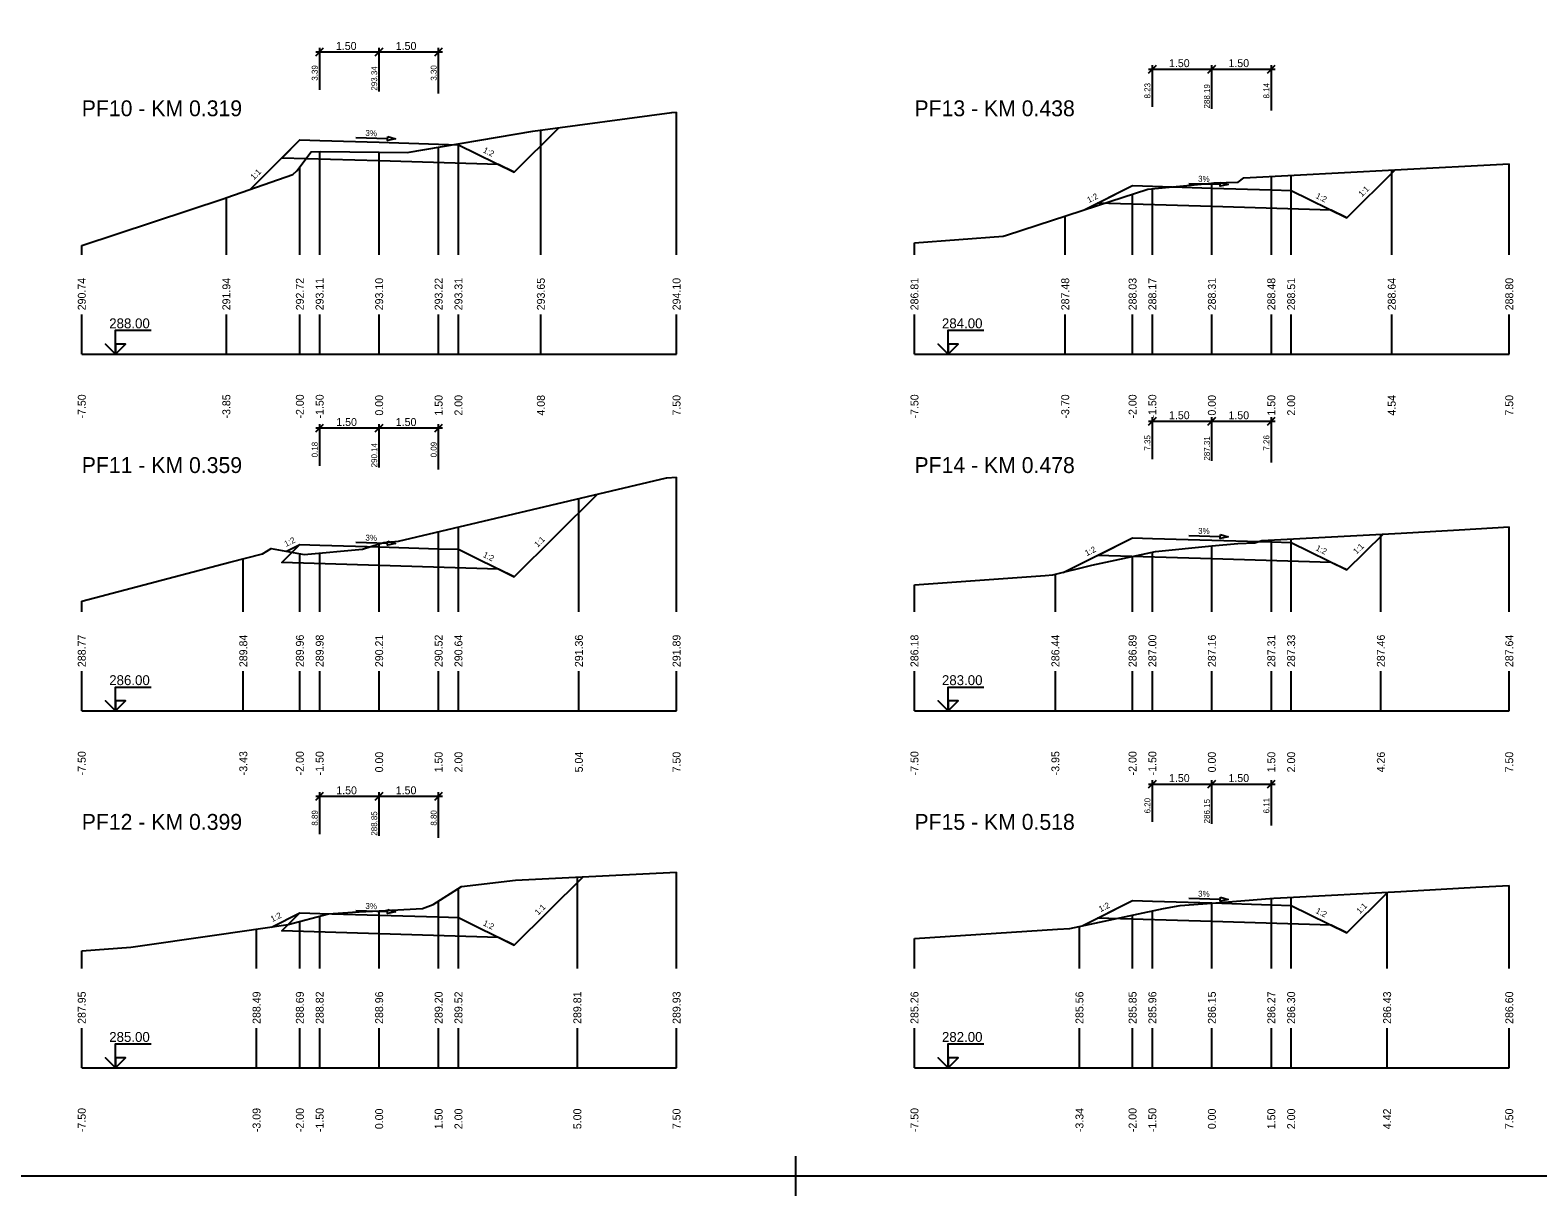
# Model space of a CAD drawing. Extents: x -5 to 1265, y -2 to 602.
# Drawn here: x 647 to 1027.2, y -2.3 to 291.7 of the extents above; entities that cross this region are included whole.
import ezdxf

# ---------------------------------------------------------------- set-up
doc = ezdxf.new("R2010")
doc.units = 0
for name, color, linetype in [('KOTA', 7, 'Continuous'), ('KOTA_DELKY', 7, 'Continuous'), ('KOTA_DELKY_CONT', 7, 'Continuous'), ('NS_TELESO_VOZOVKY', 7, 'Continuous'), ('NS_V_PF', 7, 'Continuous'), ('REZY_PF_PUVODNI', 7, 'Continuous'), ('SESTAVY_REZU_PF', 7, 'Continuous'), ('SKLON', 7, 'Continuous'), ('SVK', 7, 'Continuous')]:
    doc.layers.add(name, color=color, linetype=linetype)

msp = doc.modelspace()

# ---------------------------------------------------------------- linework, layer by layer
for p, q in [((840, 7.67), (840, -2.33)), ((840, 7.67), (840, -2.33)), ((840, 7.67), (840, -2.33)), ((840, 7.67), (840, -2.33)), ((840, 7.67), (840, -2.33)), ((840, 7.67), (840, -2.33)), ((840, 7.67), (840, -2.33)), ((840, 7.67), (840, -2.33)), ((840, 7.67), (840, -2.33)), ((840, 7.67), (840, -2.33)), ((840, 7.67), (840, -2.33)), ((840, 7.67), (840, -2.33)), ((845, 2.67), (835, 2.67)), ((845, 2.67), (835, 2.67)), ((845, 2.67), (835, 2.67)), ((845, 2.67), (835, 2.67)), ((845, 2.67), (835, 2.67)), ((845, 2.67), (835, 2.67)), ((845, 2.67), (835, 2.67)), ((845, 2.67), (835, 2.67)), ((845, 2.67), (835, 2.67)), ((845, 2.67), (835, 2.67)), ((845, 2.67), (835, 2.67)), ((845, 2.67), (835, 2.67))]:
    msp.add_line(p, q)
msp.add_lwpolyline([(0, 596.67), (1260, 596.67), (1260, 2.67), (0, 2.67)], close=True)
at = {"layer": 'KOTA'}
for points in [[(668.51, 210), (666.01, 212.5), (668.51, 210), (668.51, 216), (677.51, 216)], [(878.51, 210), (876.01, 212.5), (878.51, 210), (878.51, 216), (887.51, 216)], [(668.51, 210), (671.01, 212.5), (668.51, 212.5), (668.51, 210)], [(668.51, 210), (671.01, 212.5), (668.51, 212.5)], [(878.51, 210), (881.01, 212.5), (878.51, 212.5), (878.51, 210)], [(878.51, 210), (881.01, 212.5), (878.51, 212.5)], [(668.51, 120), (666.01, 122.5), (668.51, 120), (668.51, 126), (677.51, 126)], [(878.51, 120), (876.01, 122.5), (878.51, 120), (878.51, 126), (887.51, 126)], [(668.51, 120), (671.01, 122.5), (668.51, 122.5), (668.51, 120)], [(668.51, 120), (671.01, 122.5), (668.51, 122.5)], [(878.51, 120), (881.01, 122.5), (878.51, 122.5), (878.51, 120)], [(878.51, 120), (881.01, 122.5), (878.51, 122.5)], [(668.51, 30), (666.01, 32.5), (668.51, 30), (668.51, 36), (677.51, 36)], [(878.51, 30), (876.01, 32.5), (878.51, 30), (878.51, 36), (887.51, 36)], [(668.51, 30), (671.01, 32.5), (668.51, 32.5), (668.51, 30)], [(668.51, 30), (671.01, 32.5), (668.51, 32.5)], [(878.51, 30), (881.01, 32.5), (878.51, 32.5), (878.51, 30)], [(878.51, 30), (881.01, 32.5), (878.51, 32.5)]]:
    msp.add_lwpolyline(points, dxfattribs=at)
at = {"layer": 'KOTA_DELKY'}
for points in [[(719, 285.22), (721, 287.22)], [(719, 286.22), (736, 286.22)], [(720, 276.67), (720, 287.22)], [(734, 285.22), (736, 287.22)], [(734, 285.22), (736, 287.22)], [(734, 286.22), (751, 286.22)], [(735, 276.22), (735, 287.22)], [(735, 276.22), (735, 287.22)], [(749, 285.22), (751, 287.22)], [(750, 275.77), (750, 287.22)], [(929, 280.89), (931, 282.89)], [(929, 281.89), (946, 281.89)], [(930, 272.34), (930, 282.89)], [(944, 280.89), (946, 282.89)], [(944, 280.89), (946, 282.89)], [(944, 281.89), (961, 281.89)], [(945, 271.89), (945, 282.89)], [(945, 271.89), (945, 282.89)], [(959, 280.89), (961, 282.89)], [(960, 271.44), (960, 282.89)], [(929, 192.07), (931, 194.07)], [(930, 183.52), (930, 194.07)], [(944, 192.07), (946, 194.07)], [(944, 192.07), (946, 194.07)], [(945, 183.07), (945, 194.07)], [(945, 183.07), (945, 194.07)], [(959, 192.07), (961, 194.07)], [(960, 182.62), (960, 194.07)], [(719, 190.36), (721, 192.36)], [(719, 191.36), (736, 191.36)], [(720, 181.81), (720, 192.36)], [(734, 190.36), (736, 192.36)], [(734, 190.36), (736, 192.36)], [(734, 191.36), (751, 191.36)], [(735, 181.36), (735, 192.36)], [(735, 181.36), (735, 192.36)], [(749, 190.36), (751, 192.36)], [(750, 180.91), (750, 192.36)], [(929, 193.07), (946, 193.07)], [(944, 193.07), (961, 193.07)], [(719, 97.46), (721, 99.46)], [(720, 88.91), (720, 99.46)], [(734, 97.46), (736, 99.46)], [(734, 97.46), (736, 99.46)], [(735, 88.46), (735, 99.46)], [(735, 88.46), (735, 99.46)], [(749, 97.46), (751, 99.46)], [(750, 88.01), (750, 99.46)], [(929, 100.55), (931, 102.55)], [(929, 101.55), (946, 101.55)], [(930, 92), (930, 102.55)], [(944, 100.55), (946, 102.55)], [(944, 100.55), (946, 102.55)], [(944, 101.55), (961, 101.55)], [(945, 91.55), (945, 102.55)], [(945, 91.55), (945, 102.55)], [(959, 100.55), (961, 102.55)], [(960, 91.1), (960, 102.55)], [(719, 98.46), (736, 98.46)], [(734, 98.46), (751, 98.46)]]:
    msp.add_lwpolyline(points, dxfattribs=at)
at = {"layer": 'NS_TELESO_VOZOVKY'}
for points in [[(735, 263.42), (750, 262.97), (755, 262.82), (769.01, 255.89), (765.11, 257.82), (735, 258.72), (710.44, 259.46), (715, 264.02), (720, 263.87), (735, 263.42)], [(945, 251.89), (960, 251.44), (965, 251.29), (979.01, 244.36), (975.11, 246.28), (945, 247.19), (916.13, 248.05), (925, 252.49), (930, 252.34), (945, 251.89)], [(945, 163.07), (960, 162.62), (965, 162.47), (979.01, 155.54), (975.11, 157.46), (945, 158.37), (916.13, 159.23), (925, 163.67), (930, 163.52), (945, 163.07)], [(735, 161.36), (750, 160.91), (755, 160.76), (769.01, 153.83), (765.11, 155.75), (735, 156.66), (710.44, 157.39), (715, 161.96), (720, 161.81), (735, 161.36)], [(735, 68.46), (750, 68.01), (755, 67.86), (769.01, 60.92), (765.11, 62.85), (735, 63.76), (710.44, 64.49), (715, 69.06), (720, 68.91), (735, 68.46)], [(945, 71.55), (960, 71.1), (965, 70.95), (979.01, 64.02), (975.11, 65.95), (945, 66.85), (916.13, 67.72), (925, 72.15), (930, 72), (945, 71.55)]]:
    msp.add_lwpolyline(points, dxfattribs=at)
at = {"layer": 'NS_V_PF'}
for points in [[(702.5, 251.53), (715, 264.02), (720, 263.87), (735, 263.42), (750, 262.97), (755, 262.82), (769.01, 255.89), (780.35, 267.11)], [(912.82, 246.4), (925, 252.49), (930, 252.34), (945, 251.89), (960, 251.44), (965, 251.29), (979.01, 244.36), (991.25, 256.48)], [(711.6, 160.26), (715, 161.96), (720, 161.81), (735, 161.36), (750, 160.91), (755, 160.76), (769.01, 153.83), (790.07, 174.68)], [(907.54, 154.94), (925, 163.67), (930, 163.52), (945, 163.07), (960, 162.62), (965, 162.47), (979.01, 155.54), (988.16, 164.59)], [(707.85, 65.48), (715, 69.06), (720, 68.91), (735, 68.46), (750, 68.01), (755, 67.86), (769.01, 60.92), (786.41, 78.15)], [(912.29, 65.79), (925, 72.15), (930, 72), (945, 71.55), (960, 71.1), (965, 70.95), (979.01, 64.02), (989.41, 74.31)]]:
    msp.add_lwpolyline(points, dxfattribs=at)
at = {"layer": 'REZY_PF_PUVODNI'}
for points in [[(660, 237.41), (695.94, 249.22), (696.61, 249.46), (713.21, 255.28), (714.28, 256.24), (717.84, 261.04), (720.19, 261.14), (735, 260.97), (742.05, 260.88), (773.75, 266.24), (808.8, 270.91), (810, 271)], [(870, 238.09), (892.4, 239.76), (893.21, 240.02), (916.12, 247.47), (928.82, 251.57), (945, 253.14), (945, 253.14), (945.48, 253.19), (951.62, 253.4), (953.05, 254.48), (991.15, 256.47), (1020, 257.98)], [(660, 147.68), (697.37, 157.48), (705.58, 159.64), (707.74, 160.98), (716.1, 159.41), (730.84, 160.8), (735, 162.11), (736.18, 162.48), (739.91, 162.8), (807.5, 178.8), (807.55, 178.82), (810, 178.93)], [(870, 151.77), (902.92, 154.14), (904.89, 154.28), (914.69, 156.72), (930.75, 160.18), (945, 161.6), (951.52, 162.26), (955.87, 162.42), (957.63, 162.94), (992.77, 164.84), (1007.34, 165.63), (1020, 166.43)], [(660, 59.5), (672.37, 60.43), (694.07, 63.52), (712.04, 66.08), (722.25, 68.81), (728.29, 69.23), (735, 69.56), (745.96, 70.11), (748.61, 71.15), (755.76, 75.74), (769.41, 77.32), (784.52, 78.06), (810, 79.3)], [(870, 62.59), (906.03, 64.92), (909.17, 65.13), (932.77, 70.17), (936.99, 70.9), (945, 71.52), (945, 71.52), (960.63, 72.74), (964.03, 72.94), (992.63, 74.48), (1011.55, 75.51), (1020, 75.98)]]:
    msp.add_lwpolyline(points, dxfattribs=at)
at = {"layer": 'SESTAVY_REZU_PF'}
for points in [[(660, 210), (810, 210)], [(870, 210), (1020, 210)], [(660, 120), (810, 120)], [(870, 120), (1020, 120)], [(660, 30), (810, 30)], [(870, 30), (1020, 30)]]:
    msp.add_lwpolyline(points, dxfattribs=at)
at = {"layer": 'SKLON'}
for points in [[(729.15, 264.6), (737.14, 264.36)], [(737.16, 264.86), (739.14, 264.3), (737.13, 263.86), (737.16, 264.86)], [(939.15, 253.06), (947.14, 252.82)], [(947.16, 253.32), (949.14, 252.76), (947.13, 252.32), (947.16, 253.32)], [(939.15, 164.24), (947.14, 164)], [(947.16, 164.5), (949.14, 163.94), (947.13, 163.5), (947.16, 164.5)], [(729.15, 162.53), (737.14, 162.29)], [(737.16, 162.79), (739.14, 162.23), (737.13, 161.79), (737.16, 162.79)], [(939.15, 72.73), (947.14, 72.49)], [(947.16, 72.98), (949.14, 72.43), (947.13, 71.99), (947.16, 72.98)], [(729.15, 69.63), (737.14, 69.39)], [(737.16, 69.89), (739.14, 69.33), (737.13, 68.89), (737.16, 69.89)]]:
    msp.add_lwpolyline(points, dxfattribs=at)
for points in [[(737.16, 264.86), (739.14, 264.3), (737.13, 263.86)], [(947.16, 253.32), (949.14, 252.76), (947.13, 252.32)], [(947.16, 164.5), (949.14, 163.94), (947.13, 163.5)], [(737.16, 162.79), (739.14, 162.23), (737.13, 161.79)], [(947.16, 72.98), (949.14, 72.43), (947.13, 71.99)], [(737.16, 69.89), (739.14, 69.33), (737.13, 68.89)]]:
    msp.add_lwpolyline(points, close=True, dxfattribs=at)
at = {"layer": 'SVK'}
for points in [[(810, 235), (810, 271)], [(775.78, 235), (775.78, 266.51)], [(755, 235), (755, 263.07)], [(720, 235), (720, 261.13)], [(735, 235), (735, 260.97)], [(750, 235), (750, 262.22)], [(715, 235), (715, 257.21)], [(960, 235), (960, 254.84)], [(965, 235), (965, 255.11)], [(990.36, 235), (990.36, 256.43)], [(1020, 235), (1020, 257.98)], [(930, 235), (930, 251.69)], [(945, 235), (945, 253.14)], [(696.47, 235), (696.47, 249.41)], [(925, 235), (925, 250.34)], [(908.02, 235), (908.02, 244.84)], [(660, 235), (660, 237.41)], [(870, 235), (870, 238.09)], [(660, 210), (660, 220)], [(696.47, 210), (696.47, 220)], [(715, 210), (715, 220)], [(720, 210), (720, 220)], [(735, 210), (735, 220)], [(750, 210), (750, 220)], [(755, 210), (755, 220)], [(775.78, 210), (775.78, 220)], [(810, 210), (810, 220)], [(870, 210), (870, 220)], [(908.02, 210), (908.02, 220)], [(925, 210), (925, 220)], [(930, 210), (930, 220)], [(945, 210), (945, 220)], [(960, 210), (960, 220)], [(965, 210), (965, 220)], [(990.36, 210), (990.36, 220)], [(1020, 210), (1020, 220)], [(810, 145), (810, 178.93)], [(785.37, 145), (785.37, 173.57)], [(750, 145), (750, 165.19)], [(755, 145), (755, 166.38)], [(987.62, 145), (987.62, 164.56)], [(1020, 145), (1020, 166.43)], [(720, 145), (720, 159.78)], [(735, 145), (735, 162.11)], [(930, 145), (930, 160.02)], [(945, 145), (945, 161.6)], [(960, 145), (960, 163.06)], [(965, 145), (965, 163.34)], [(700.74, 145), (700.74, 158.37)], [(715, 145), (715, 159.62)], [(925, 145), (925, 158.94)], [(905.54, 145), (905.54, 154.44)], [(870, 145), (870, 151.77)], [(660, 145), (660, 147.68)], [(660, 120), (660, 130)], [(700.74, 120), (700.74, 130)], [(715, 120), (715, 130)], [(720, 120), (720, 130)], [(735, 120), (735, 130)], [(750, 120), (750, 130)], [(755, 120), (755, 130)], [(785.37, 120), (785.37, 130)], [(810, 120), (810, 130)], [(870, 120), (870, 130)], [(905.54, 120), (905.54, 130)], [(925, 120), (925, 130)], [(930, 120), (930, 130)], [(945, 120), (945, 130)], [(960, 120), (960, 130)], [(965, 120), (965, 130)], [(987.62, 120), (987.62, 130)], [(1020, 120), (1020, 130)], [(784.98, 55), (784.98, 78.08)], [(810, 55), (810, 79.3)], [(755, 55), (755, 75.25)], [(960, 55), (960, 72.69)], [(965, 55), (965, 72.99)], [(989.2, 55), (989.2, 74.3)], [(1020, 55), (1020, 75.98)], [(735, 55), (735, 69.56)], [(750, 55), (750, 72.04)], [(925, 55), (925, 68.51)], [(930, 55), (930, 69.58)], [(945, 55), (945, 71.52)], [(704.08, 55), (704.08, 64.94)], [(715, 55), (715, 66.87)], [(720, 55), (720, 68.21)], [(911.61, 55), (911.61, 65.65)], [(870, 55), (870, 62.59)], [(660, 55), (660, 59.5)], [(660, 30), (660, 40)], [(704.08, 30), (704.08, 40)], [(715, 30), (715, 40)], [(720, 30), (720, 40)], [(735, 30), (735, 40)], [(750, 30), (750, 40)], [(755, 30), (755, 40)], [(784.98, 30), (784.98, 40)], [(810, 30), (810, 40)], [(870, 30), (870, 40)], [(911.61, 30), (911.61, 40)], [(925, 30), (925, 40)], [(930, 30), (930, 40)], [(945, 30), (945, 40)], [(960, 30), (960, 40)], [(965, 30), (965, 40)], [(989.2, 30), (989.2, 40)], [(1020, 30), (1020, 40)]]:
    msp.add_lwpolyline(points, dxfattribs=at)

# ---------------------------------------------------------------- texts
at = {"layer": 'KOTA'}
for s, p in [('288.00', (666.93, 216.5)), ('284.00', (876.93, 216.5)), ('286.00', (666.93, 126.5)), ('283.00', (876.93, 126.5)), ('285.00', (666.93, 36.5)), ('282.00', (876.93, 36.5))]:
    msp.add_text(s, height=2.5, dxfattribs=at).set_placement(p)
at = {"layer": 'KOTA_DELKY'}
for p in [(724.1, 286.72), (739.19, 286.72), (934.19, 282.39), (949.19, 282.39), (934.19, 193.57), (949.19, 193.57), (724.19, 191.86), (739.19, 191.86), (934.19, 102.05), (949.19, 102.05), (724.19, 98.96), (739.19, 98.96)]:
    msp.add_text('1.50', height=2, dxfattribs=at).set_placement(p)
at = {"layer": 'KOTA_DELKY_CONT'}
for s, p in [('3.39', (719.5, 278.97)), ('293.34', (734.5, 276.46)), ('3.30', (749.5, 278.97)), ('8.23', (929.5, 274.48)), ('288.19', (944.5, 271.96)), ('8.14', (959.5, 274.48)), ('0.18', (719.5, 183.95)), ('290.14', (734.5, 181.43)), ('0.09', (749.5, 183.95)), ('7.35', (929.5, 185.66)), ('287.31', (944.5, 183.14)), ('7.26', (959.5, 185.66)), ('6.20', (929.5, 94.14)), ('286.15', (944.5, 91.63)), ('6.11', (959.5, 94.14)), ('8.89', (719.5, 91.05)), ('288.85', (734.5, 88.53)), ('8.80', (749.5, 91.05))]:
    msp.add_text(s, height=1.5, rotation=90, dxfattribs=at).set_placement(p)
at = {"layer": 'SESTAVY_REZU_PF'}
for s, p in [('PF10 - KM 0.319', (660, 270)), ('PF13 - KM 0.438', (870, 270)), ('PF11 - KM 0.359', (660, 180)), ('PF14 - KM 0.478', (870, 180)), ('PF12 - KM 0.399', (660, 90)), ('PF15 - KM 0.518', (870, 90))]:
    msp.add_text(s, height=4, dxfattribs=at).set_placement(p)
at = {"layer": 'SKLON'}
for s, rotation, p in [('3%', 358.2816, (731.52, 265.03)), ('1:2', 333.679, (761.04, 260.95)), ('1:1', 45, (703.42, 253.85)), ('3%', 358.2816, (941.52, 253.49)), ('1:1', 44.7149, (982.84, 249.55)), ('1:2', 26.5651, (913.97, 248.09)), ('1:2', 333.679, (971.04, 249.42)), ('1:2', 26.5651, (711.52, 161.34)), ('3%', 358.2816, (731.52, 162.96)), ('1:1', 44.7149, (774.98, 161.14)), ('3%', 358.2816, (941.52, 164.67)), ('1:2', 333.679, (761.04, 158.89)), ('1:2', 26.5651, (913.44, 159.01)), ('1:2', 333.679, (971.04, 160.6)), ('1:1', 44.7149, (981.5, 159.4)), ('3%', 358.2816, (941.52, 73.15)), ('1:2', 26.5651, (708.07, 66.71)), ('3%', 358.2816, (731.52, 70.06)), ('1:1', 44.7149, (775.13, 68.39)), ('1:2', 26.5651, (916.93, 69.23)), ('1:2', 333.679, (971.04, 69.08)), ('1:1', 44.7149, (982.31, 68.69)), ('1:2', 333.679, (761.04, 65.99))]:
    msp.add_text(s, height=1.5, rotation=rotation, dxfattribs=at).set_placement(p)
at = {"layer": 'SVK'}
for s, p in [(' 290.74', (661, 220.3)), (' 291.94', (697.47, 220.3)), (' 292.72', (716, 220.3)), (' 293.11', (721, 220.3)), (' 293.10', (736, 220.3)), (' 293.22', (751, 220.3)), (' 293.31', (756, 220.3)), (' 293.65', (776.78, 220.3)), (' 294.10', (811, 220.3)), (' 286.81', (871, 220.3)), (' 287.48', (909.02, 220.3)), (' 288.03', (926, 220.3)), (' 288.17', (931, 220.3)), (' 288.31', (946, 220.3)), (' 288.48', (961, 220.3)), (' 288.51', (966, 220.3)), (' 288.64', (991.36, 220.3)), (' 288.80', (1021, 220.3)), (' -7.50', (661, 193)), (' -3.85', (697.47, 193)), (' -2.00', (716, 193)), (' -1.50', (721, 193)), ('  0.00', (736, 193)), ('  1.50', (751, 193)), ('  2.00', (756, 193)), ('  4.08', (776.78, 193)), ('  7.50', (811, 193)), (' -7.50', (871, 193)), (' -3.70', (909.02, 193)), (' -2.00', (926, 193)), (' -1.50', (931, 193)), ('  0.00', (946, 193)), ('  1.50', (961, 193)), ('  2.00', (966, 193)), ('  4.54', (991.36, 193)), ('  7.50', (1021, 193)), (' 288.77', (661, 130.3)), (' 289.84', (701.74, 130.3)), (' 289.96', (716, 130.3)), (' 289.98', (721, 130.3)), (' 290.21', (736, 130.3)), (' 290.52', (751, 130.3)), (' 290.64', (756, 130.3)), (' 291.36', (786.37, 130.3)), (' 291.89', (811, 130.3)), (' 286.18', (871, 130.3)), (' 286.44', (906.54, 130.3)), (' 286.89', (926, 130.3)), (' 287.00', (931, 130.3)), (' 287.16', (946, 130.3)), (' 287.31', (961, 130.3)), (' 287.33', (966, 130.3)), (' 287.46', (988.62, 130.3)), (' 287.64', (1021, 130.3)), (' -7.50', (661, 103)), (' -3.43', (701.74, 103)), (' -2.00', (716, 103)), (' -1.50', (721, 103)), ('  0.00', (736, 103)), ('  1.50', (751, 103)), ('  2.00', (756, 103)), ('  5.04', (786.37, 103)), ('  7.50', (811, 103)), (' -7.50', (871, 103)), (' -3.95', (906.54, 103)), (' -2.00', (926, 103)), (' -1.50', (931, 103)), ('  0.00', (946, 103)), ('  1.50', (961, 103)), ('  2.00', (966, 103)), ('  4.26', (988.62, 103)), ('  7.50', (1021, 103)), (' 287.95', (661, 40.3)), (' 288.49', (705.08, 40.3)), (' 288.69', (716, 40.3)), (' 288.82', (721, 40.3)), (' 288.96', (736, 40.3)), (' 289.20', (751, 40.3)), (' 289.52', (756, 40.3)), (' 289.81', (785.98, 40.3)), (' 289.93', (811, 40.3)), (' 285.26', (871, 40.3)), (' 285.56', (912.61, 40.3)), (' 285.85', (926, 40.3)), (' 285.96', (931, 40.3)), (' 286.15', (946, 40.3)), (' 286.27', (961, 40.3)), (' 286.30', (966, 40.3)), (' 286.43', (990.2, 40.3)), (' 286.60', (1021, 40.3)), (' -7.50', (661, 13)), (' -3.09', (705.08, 13)), (' -2.00', (716, 13)), (' -1.50', (721, 13)), ('  0.00', (736, 13)), ('  1.50', (751, 13)), ('  2.00', (756, 13)), ('  5.00', (785.98, 13)), ('  7.50', (811, 13)), (' -7.50', (871, 13)), (' -3.34', (912.61, 13)), (' -2.00', (926, 13)), (' -1.50', (931, 13)), ('  0.00', (946, 13)), ('  1.50', (961, 13)), ('  2.00', (966, 13)), ('  4.42', (990.2, 13)), ('  7.50', (1021, 13))]:
    msp.add_text(s, height=2, rotation=90, dxfattribs=at).set_placement(p)

doc.saveas('drawing.dxf')
